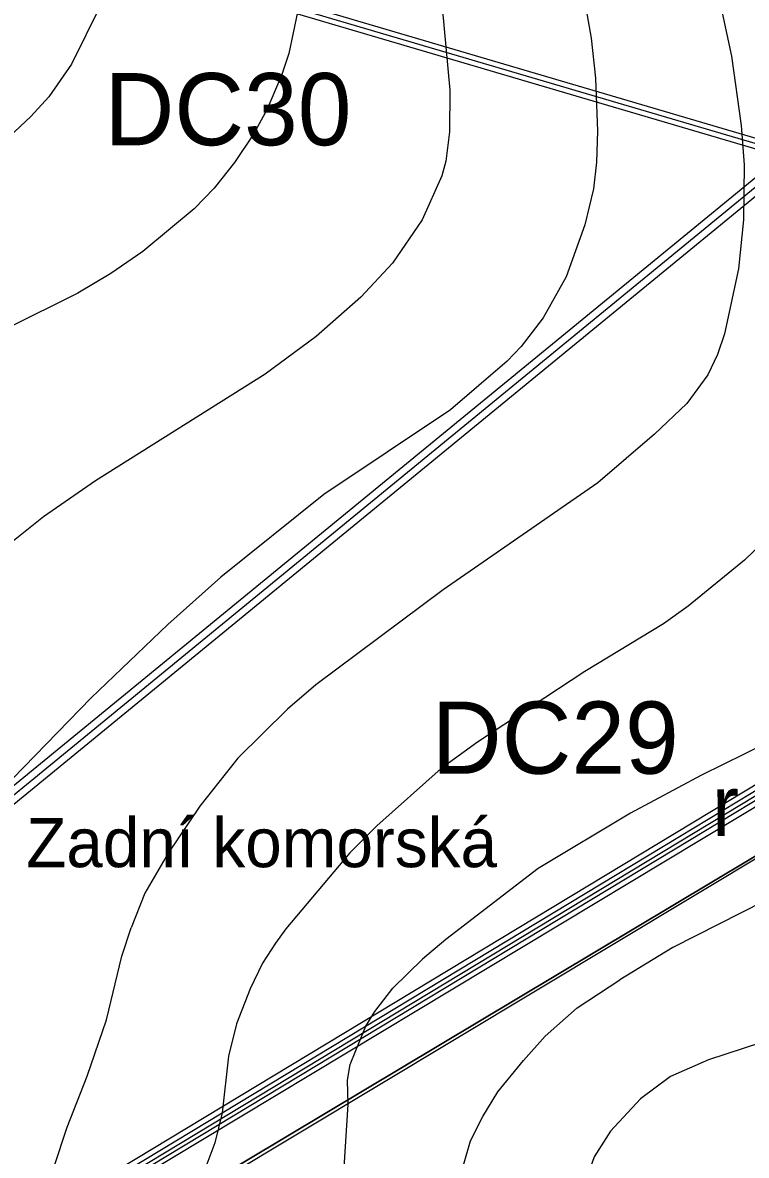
# Model space of a CAD drawing. Extents: x -1900516 to -575031, y -3809306 to -1157387.
# Drawn here: x -577352.9 to -577102.4, y -1159141.1 to -1158748.8 of the extents above; entities that cross this region are included whole.
import ezdxf

# ---------------------------------------------------------------- set-up
doc = ezdxf.new("R2010")
doc.units = 0
for name, color, linetype in [('01_MÍSTNÍ_NÁZVY', 7, 'Continuous'), ('01_PARCELY_NÁVRH_PC', 7, 'Continuous'), ('01_VRSTEVNICE', 7, 'Continuous'), ('02_KULTURY STAV', 7, 'Continuous'), ('03_PC_NÁVRH', 7, 'Continuous'), ('03_PC_POPIS_NÁVRH', 7, 'Continuous'), ('04_ZPF_OP_ORGAN', 7, 'Continuous'), ('06_ÚSES_BK', 7, 'Continuous'), ('07_OCH_P A POPISY TI', 7, 'Continuous'), ('07_VODOVOD', 7, 'Continuous')]:
    doc.layers.add(name, color=color, linetype=linetype)

msp = doc.modelspace()

# ---------------------------------------------------------------- linework, layer by layer
at = {"layer": '01_PARCELY_NÁVRH_PC'}
for points in [[(-577091.99, -1158790.99), (-577585.54, -1158645.46), (-577589.82, -1158643.01), (-577593.34, -1158638.12), (-577582.32, -1158668.78), (-577582.25, -1158662.46), (-577579.54, -1158657.99), (-577573.8, -1158654.54), (-577566.93, -1158654.59), (-577092.95, -1158794.35), (-577022.53, -1158810.48), (-577021, -1158807.33)], [(-577342.69, -1159165.38), (-577345.04, -1159166.81), (-577347.21, -1159168.13), (-577350.17, -1159163.07), (-577351.76, -1159160.35), (-577343.62, -1159162.43), (-577125.54, -1159030.6), (-576902.3, -1158895.66), (-576899.87, -1158897.69), (-577122.14, -1159032.05), (-577342.11, -1159165.03)]]:
    msp.add_lwpolyline(points, close=True, dxfattribs=at)
at = {"layer": '01_VRSTEVNICE'}
for points in [[(-577159.9, -1158732.48), (-577156.09, -1158754.21), (-577154.68, -1158768.04), (-577153.97, -1158786.38), (-577154.25, -1158797.1), (-577155.38, -1158806.42), (-577158.34, -1158818.83), (-577164.84, -1158836.89), (-577172.74, -1158851), (-577180.36, -1158861.02), (-577185.15, -1158866.1), (-577204.77, -1158882.89), (-577248.65, -1158912.24), (-577284.34, -1158940.88), (-577302.68, -1158957.24), (-577329.21, -1158982.64), (-577387.62, -1159042.6), (-577395.61, -1159053.76)], [(-577030.37, -1158731.35), (-577008.79, -1158772.83), (-577001.45, -1158786.66), (-576993.7, -1158798.96), (-576989.03, -1158810.65), (-576985.79, -1158828.43), (-576984.38, -1158840.56), (-576984.1, -1158849.31), (-576985.79, -1158865.11), (-576988.75, -1158876.96), (-576993.69, -1158888.81), (-577001.87, -1158904.62), (-577009.35, -1158916.47), (-577021.48, -1158932.27), (-577035.03, -1158947.93), (-577050.55, -1158964.58), (-577071.43, -1158982.92), (-577082.72, -1158990.82), (-577095.42, -1158998.3), (-577117.99, -1159009.45), (-577142.54, -1159022.57), (-577174.43, -1159041.76), (-577206.46, -1159066.31), (-577214.52, -1159073.12)], [(-577071.71, -1158738.41), (-577063.95, -1158758.16), (-577056.62, -1158787.23), (-577052.39, -1158814.88), (-577052.1, -1158838.58), (-577053.37, -1158850.72), (-577055.35, -1158862.01), (-577058.73, -1158874.7), (-577061.98, -1158883.17), (-577070.45, -1158899.68), (-577084.13, -1158916.75), (-577103.04, -1158934.95), (-577122.51, -1158950.89), (-577131.11, -1158956.96), (-577158.35, -1158973.47), (-577195.45, -1158998.02), (-577208.01, -1159007.05), (-577230.3, -1159026.94), (-577239.61, -1159036.26), (-577261.84, -1159062.63), (-577265.36, -1159067.59)], [(-577325.96, -1158742.92), (-577335.98, -1158763.24), (-577343.88, -1158774.53), (-577350.09, -1158781.3), (-577365.19, -1158795.41)], [(-577207.73, -1158743.49), (-577205.05, -1158772.27), (-577205.19, -1158786.66), (-577206.46, -1158796.82), (-577207.87, -1158801.9), (-577214.64, -1158817.14), (-577224.94, -1158832.09), (-577235.81, -1158843.95), (-577251.33, -1158857.49), (-577268.96, -1158870.61), (-577327.66, -1158907.44), (-577345.72, -1158920), (-577363.64, -1158934.25)], [(-576990.3, -1158744.62), (-576978.03, -1158756.19), (-576960.11, -1158779.04), (-576944.31, -1158804.44), (-576937.68, -1158821.37), (-576933.44, -1158838.3), (-576930.76, -1158855.23), (-576929.92, -1158867.93), (-576931.19, -1158889.1), (-576934.71, -1158903.06), (-576938.81, -1158912.38), (-576943.89, -1158920.28), (-576955.45, -1158934.25), (-576996.94, -1158976.85), (-577015.14, -1158998.16), (-577034.04, -1159016.64), (-577056.76, -1159032.87), (-577072.56, -1159042.18), (-577096.27, -1159053.04), (-577127.87, -1159069.13), (-577146.21, -1159080.25)], [(-577257.82, -1158745.18), (-577260.78, -1158759.57), (-577263.32, -1158767.19), (-577268.4, -1158779.04), (-577273.05, -1158787.51), (-577279.54, -1158797.24), (-577286.6, -1158806.13), (-577293.51, -1158813.33), (-577311.29, -1158828.14), (-577322.44, -1158835.76), (-577333.86, -1158842.53), (-577358.13, -1158854.67)], [(-577110.8, -1158745.46), (-577107.55, -1158760.42), (-577104.17, -1158784.41), (-577103.18, -1158798.09), (-577103.46, -1158817.14), (-577105.15, -1158834.07), (-577109.95, -1158856.64), (-577112.35, -1158863.7), (-577115.73, -1158870.75), (-577123.07, -1158880.77), (-577134.22, -1158891.35), (-577153.83, -1158908.14), (-577207.31, -1158945.25), (-577251.47, -1158978.12), (-577261.2, -1158986.59), (-577278.47, -1159003.49), (-577291.54, -1159020.17), (-577302.54, -1159036.4), (-577310.58, -1159050.22), (-577315.38, -1159062.27)], [(-577354.38, -1159212.37), (-577352.42, -1159198.95), (-577351.3, -1159181.61), (-577349.62, -1159170.43), (-577346.69, -1159159.24), (-577337.46, -1159131.28), (-577330.61, -1159113.66), (-577323.9, -1159094.08), (-577318.57, -1159072.06), (-577315.38, -1159062.27)], [(-577265.36, -1159067.59), (-577269.93, -1159074.5), (-577274.2, -1159083.41), (-577278.87, -1159095.48), (-577281.67, -1159106.67), (-577283.91, -1159126.38), (-577286.36, -1159136.72), (-577293.99, -1159156.98), (-577306.98, -1159196.71), (-577314.67, -1159228.03), (-577323.2, -1159248.17), (-577341.51, -1159288.16), (-577344.83, -1159294.59), (-577348.64, -1159299.9), (-577354.8, -1159307.31)], [(-577361.23, -1159400.71), (-577346.83, -1159384.77), (-577315.51, -1159347.44), (-577307.68, -1159335.7), (-577294.53, -1159312.21), (-577278.17, -1159278.09), (-577264.05, -1159241.74), (-577255.94, -1159212.37), (-577250.07, -1159178.82), (-577243.78, -1159155.33), (-577241.68, -1159145.26), (-577240.28, -1159123.45), (-577240.42, -1159115.06), (-577239.57, -1159109.63), (-577237.63, -1159104.71), (-577234.13, -1159096.32), (-577231.06, -1159091.29), (-577224.76, -1159083.18), (-577214.52, -1159073.12)], [(-577359.41, -1159467.41), (-577350.32, -1159458.6), (-577336.9, -1159442.94), (-577302.92, -1159394.28), (-577290.06, -1159374.01), (-577255.24, -1159312.21), (-577251.61, -1159304.38), (-577224.2, -1159253.48), (-577214.97, -1159228.31), (-577210.64, -1159211.53), (-577205.89, -1159186.37), (-577200.29, -1159144.42), (-577197.92, -1159136.03), (-577193.58, -1159127.64), (-577188.41, -1159119.1), (-577179.6, -1159108.21), (-577172.05, -1159099.82), (-577161, -1159090.03), (-577146.21, -1159080.25)], [(-577064.7, -1159088.98), (-577091.51, -1159100.1), (-577115.56, -1159107.93), (-577128.71, -1159113.8), (-577139.05, -1159121.49), (-577149.4, -1159132.68), (-577155.13, -1159141.62), (-577160.58, -1159157.28), (-577164.92, -1159186.37), (-577169.95, -1159213.21), (-577177.36, -1159246.77), (-577182.12, -1159262.15), (-577188.55, -1159277.81), (-577199.88, -1159300.18), (-577229.94, -1159356.11), (-577240.56, -1159374.01), (-577272.02, -1159418.75), (-577288.1, -1159447.83), (-577301.24, -1159467.97), (-577335.78, -1159514.67), (-577346.69, -1159527.95), (-577390.87, -1159574.09)]]:
    msp.add_lwpolyline(points, dxfattribs=at)
at = {"layer": '03_PC_NÁVRH'}
msp.add_line((-577348.38, -1159167.06), (-576901.09, -1158896.68), dxfattribs=at)
msp.add_lwpolyline([(-577591.99, -1158645.38), (-577023.12, -1158813.12)], dxfattribs=at)
at = {"layer": '04_ZPF_OP_ORGAN'}
msp.add_lwpolyline([(-577350.05, -1159164.2), (-576903.86, -1158894.73), (-577022.53, -1158810.48), (-577009.99, -1158786.2), (-576892.58, -1158838.93), (-576871.91, -1158799.96), (-577005.93, -1158719.17), (-577009.6, -1158721.31), (-577178.26, -1158431.99), (-577189.42, -1158416.79), (-577219.92, -1158422.77), (-577242.89, -1158431.88), (-577294.41, -1158455.68), (-577323.82, -1158465.16), (-577429.53, -1158496.15), (-577519.46, -1158523.89), (-577547.21, -1158534.99), (-577564.81, -1158545.04), (-577613.08, -1158585.53), (-577524.43, -1158834.12), (-577501.85, -1158879.88), (-577349.53, -1159162.53)], close=True, dxfattribs=at)
msp.add_lwpolyline([(-577350.05, -1159164.2), (-576903.86, -1158894.73), (-577022.53, -1158810.48), (-577009.99, -1158786.2), (-576892.58, -1158838.93), (-576871.91, -1158799.96), (-577005.93, -1158719.17), (-577009.6, -1158721.31), (-577178.26, -1158431.99), (-577189.42, -1158416.79), (-577219.92, -1158422.77), (-577242.89, -1158431.88), (-577294.41, -1158455.68), (-577323.82, -1158465.16), (-577429.53, -1158496.15), (-577519.46, -1158523.89), (-577547.21, -1158534.99), (-577564.81, -1158545.04), (-577613.08, -1158585.53), (-577524.43, -1158834.12), (-577501.85, -1158879.88), (-577349.53, -1159162.53)], close=True, dxfattribs=at)
for points in [[(-577329.19, -1159175.08), (-576886.04, -1158909.79), (-576861.35, -1158934.05), (-576822.98, -1158980.09), (-576793.2, -1159020.76), (-576817.91, -1159051.59), (-576582.27, -1159379.64)], [(-576582.27, -1159379.64), (-576817.91, -1159051.59), (-576793.2, -1159020.76), (-576822.98, -1158980.09), (-576861.35, -1158934.05), (-576886.04, -1158909.79), (-577329.19, -1159175.08), (-577267.49, -1159257.38)]]:
    msp.add_lwpolyline(points, dxfattribs=at)
at = {"layer": '06_ÚSES_BK'}
for p, q in [((-577351.72, -1159172.28), (-576897.46, -1158898.86)), ((-576885.27, -1158909.8), (-577326.33, -1159174.89))]:
    msp.add_line(p, q, dxfattribs=at)
at = {"layer": '07_OCH_P A POPISY TI'}
for points in [[(-576191.25, -1158057.87), (-577418.49, -1159064.24), (-577437.53, -1159075.36)], [(-576188.08, -1158061.74), (-577415.62, -1159068.35), (-577435.01, -1159079.68)]]:
    msp.add_lwpolyline(points, dxfattribs=at)
at = {"layer": '07_VODOVOD'}
msp.add_lwpolyline([(-576189.67, -1158059.8), (-577417.05, -1159066.3), (-577436.27, -1159077.52)], dxfattribs=at)

# ---------------------------------------------------------------- texts
at = {"layer": '01_MÍSTNÍ_NÁZVY'}
msp.add_text('Zadní komorská', height=17, dxfattribs=at).set_placement((-577351.69, -1159041.27))
at = {"layer": '02_KULTURY STAV'}
msp.add_text('r', height=21, dxfattribs=at).set_placement((-577114.34, -1159030.48))
msp.add_text('r', height=21, dxfattribs=at).set_placement((-577114.34, -1159030.48))
at = {"layer": '03_PC_POPIS_NÁVRH'}
for s, p in [('DC30', (-577324.57, -1158791.3)), ('DC29', (-577211.27, -1159008.91))]:
    msp.add_text(s, height=25, dxfattribs=at).set_placement(p)

doc.saveas('drawing.dxf')
